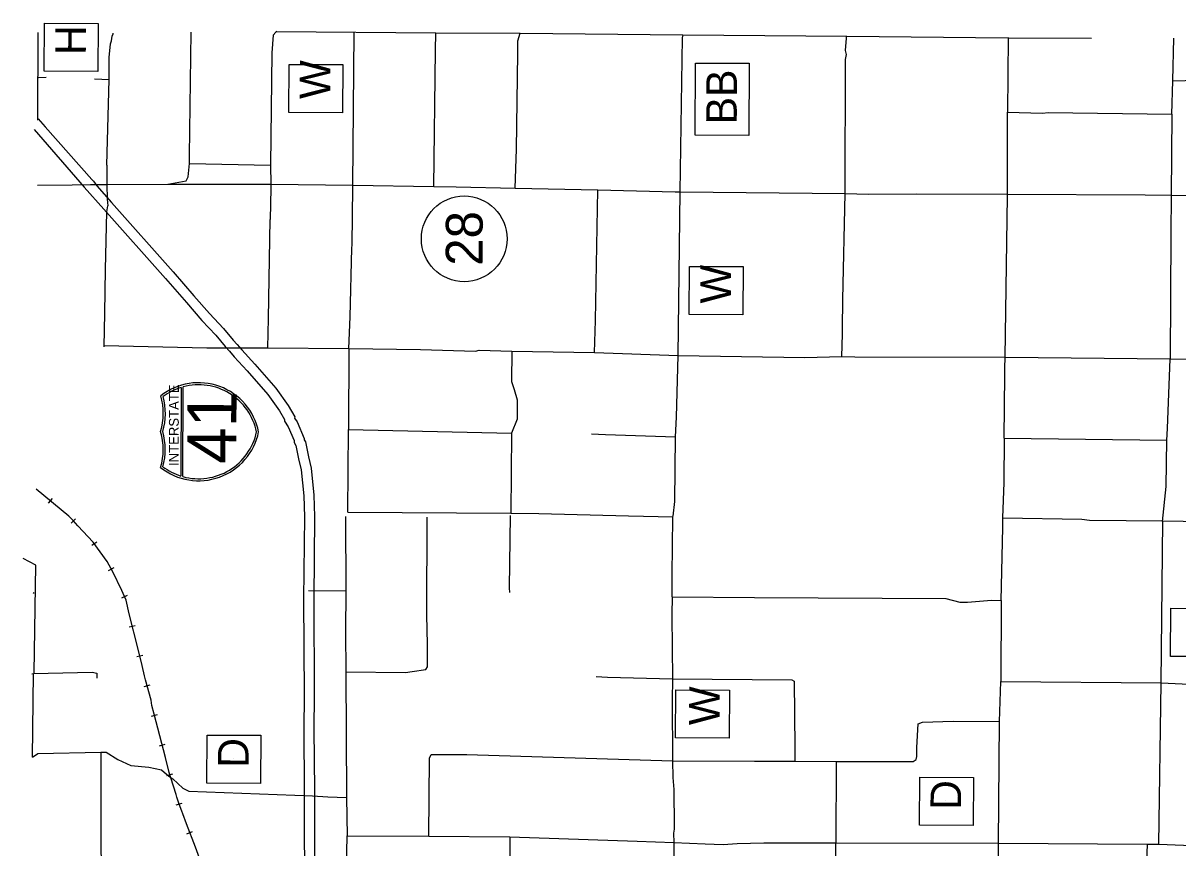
# Model space of a CAD drawing. Extents: x 299354 to 1325680, y 96128 to 228242.
# Drawn here: x 304178 to 341858, y 201335 to 228242 of the extents above; entities that cross this region are included whole.
import ezdxf

# ---------------------------------------------------------------- set-up
doc = ezdxf.new("R2010")
doc.units = 0
for name, color, linetype in [('Level 12', 7, 'Continuous'), ('Level 13', 7, 'Continuous'), ('Level 2', 7, 'Continuous'), ('Level 3', 7, 'Continuous'), ('Level 4', 7, 'Continuous')]:
    doc.layers.add(name, color=color, linetype=linetype)

msp = doc.modelspace()

# ---------------------------------------------------------------- linework, layer by layer
at = {"layer": 'Level 12'}
for p, q in [((318571, 221204), (318571, 221204)), ((309335, 216359), (309327, 213467)), ((309394, 213447), (309402, 216378))]:
    msp.add_line(p, q, dxfattribs=at)
msp.add_circle((318571, 221204), 1398, dxfattribs=at)
for centre, radius, start, end in [((309903, 214511), 1999, 11.3832, 128.1773), ((309903, 214511), 1933, 107.1012, 126.8422), ((309903, 214511), 1933, 11.7868, 105.0434), ((306754, 215504), 1999, 342.8553, 16.8422), ((306754, 215504), 2066, 343.4192, 15.5586), ((309906, 215311), 1999, 231.5152, 348.3093), ((306751, 214335), 1999, 342.8502, 16.8372), ((306751, 214335), 2066, 344.1339, 16.2733), ((309906, 215311), 1933, 254.649, 347.9057), ((309906, 215311), 1933, 232.8503, 252.5912)]:
    msp.add_arc(centre, radius, start, end, dxfattribs=at)
at = {"layer": 'Level 13'}
for p, q in [((305725, 227486), (305725, 227486)), ((313704, 226137), (313704, 226137)), ((326968, 225806), (326968, 225806)), ((326771, 219548), (326771, 219548)), ((326321, 205737), (326321, 205737)), ((311034, 204259), (311034, 204259)), ((334286, 202886), (334286, 202886))]:
    msp.add_line(p, q, dxfattribs=at)
for points in [[(306619, 226665), (304869, 226672), (304875, 228242), (306625, 228234)], [(314598, 225316), (312848, 225323), (312855, 226893), (314605, 226886)], [(327861, 224576), (326111, 224583), (326120, 226938), (327870, 226931)], [(327665, 218726), (325915, 218734), (325922, 220304), (327672, 220296)], [(343369, 207574), (341619, 207581), (341625, 209151), (343375, 209143)], [(327215, 204915), (325465, 204922), (325472, 206492), (327222, 206485)], [(311927, 203437), (310177, 203444), (310184, 205014), (311934, 205007)], [(335179, 202064), (333429, 202071), (333436, 203641), (335186, 203634)]]:
    msp.add_lwpolyline(points, close=True, dxfattribs=at)
at = {"layer": 'Level 2'}
for points in [[(314935, 222887), (314935, 222954), (314980, 227939)], [(325553, 217399), (325618, 222735), (325697, 227762), (325710, 227863)], [(304667, 225119), (304901, 224857), (306419, 223141), (306479, 223084)], [(304538, 224770), (306171, 222894)], [(306479, 223084), (306581, 222931), (307062, 222393), (309069, 220123), (309754, 219341), (310256, 218764), (310712, 218283), (311027, 217903), (311158, 217754), (311313, 217579), (311735, 217116), (312427, 216327), (312823, 215768), (313039, 215396), (313038, 215351), (313117, 215230), (313349, 214690), (313349, 214650), (313388, 214582), (313486, 214096), (313575, 213726), (313664, 212844), (313689, 212144)], [(306171, 222894), (306815, 222174), (308821, 219905), (309506, 219124), (310011, 218542), (310465, 218064), (310776, 217689), (310910, 217536), (311068, 217358), (311489, 216896), (312167, 216122), (312545, 215590), (312708, 215309), (312707, 215254), (312825, 215073), (313018, 214625), (313017, 214564), (313075, 214464), (313164, 214025), (313249, 213671), (313335, 212822), (313359, 212133)], [(306377, 222972), (306911, 222975), (308905, 222983), (311733, 222991), (312266, 222986), (314935, 222954), (317579, 222914), (318313, 222900), (320231, 222858), (322933, 222800), (325451, 222736), (325618, 222735), (330998, 222679), (331757, 222664), (333333, 222667), (336294, 222657), (340790, 222634), (341640, 222626), (346260, 222536), (346552, 222533), (348354, 222517)], [(325463, 214749), (325502, 215382), (325553, 217399)], [(325553, 217399), (329690, 217338), (330891, 217369)], [(330891, 217369), (331317, 217357), (336221, 217347)], [(336221, 217347), (341601, 217291)], [(341493, 214640), (341522, 215015), (341601, 217291)], [(341601, 217291), (346930, 217194)], [(325391, 212159), (325444, 212631), (325463, 214749)], [(341357, 211985), (341480, 213123), (341493, 214640)], [(313359, 212140), (313332, 209460), (313349, 206306), (313338, 205205), (313351, 203218), (313361, 199311)], [(313689, 212137), (313662, 209460), (313679, 206305), (313668, 205204), (313681, 203219), (313691, 199315)], [(325354, 209522), (325361, 210247), (325378, 212114)], [(341316, 206719), (341335, 208836), (341365, 212002)], [(325354, 209522), (325349, 208947), (325348, 208897), (325363, 206847)], [(304466, 207013), (304515, 207019)], [(325363, 206847), (325356, 206155), (325371, 204172)], [(341234, 201453), (341316, 206719)], [(304489, 204294), (304657, 204409), (306709, 204458)], [(306709, 204458), (306884, 204456), (307266, 204219), (307689, 204024), (308281, 203968), (308689, 203881), (308929, 203671), (309062, 203586), (309392, 203283), (309583, 203182), (313618, 203037), (314118, 202999), (314735, 202977)], [(325371, 204172), (325383, 203630), (325413, 203238), (325418, 202038), (325418, 201946), (325400, 201813)], [(314735, 202977), (314757, 201726)], [(314757, 201726), (317418, 201719)], [(317418, 201719), (320061, 201695)], [(320061, 201695), (320037, 199037), (320016, 196795), (320112, 196378)], [(320061, 201695), (324213, 201557)], [(325400, 201813), (325414, 201513)], [(324213, 201557), (325414, 201513)], [(325414, 201513), (325395, 199513), (325418, 198380), (325449, 196296)], [(325414, 201513), (326431, 201471), (327023, 201449), (327482, 201478), (328349, 201503), (330701, 201499)], [(330701, 201499), (336005, 201484)], [(336005, 201484), (340859, 201457)], [(340859, 201457), (341234, 201453)], [(341234, 201453), (343927, 201346)]]:
    msp.add_lwpolyline(points, dxfattribs=at)
at = {"layer": 'Level 3'}
for p, q in [((304660, 225072), (304668, 227932)), ((304489, 204294), (304522, 207019))]:
    msp.add_line(p, q, dxfattribs=at)
at = {"layer": 'Level 4'}
for p, q in [((341691, 226353), (341721, 227745)), ((305004, 212578), (305132, 212732)), ((305746, 211929), (305892, 212065)), ((306419, 211207), (306581, 211323)), ((306968, 210387), (307144, 210484)), ((307396, 209494), (307580, 209574)), ((307642, 208543), (307836, 208593)), ((307888, 207575), (308082, 207623)), ((308128, 206603), (308321, 206654)), ((308368, 205632), (308561, 205683)), ((308623, 204665), (308817, 204716)), ((308871, 203695), (309063, 203749)), ((309172, 202739), (309363, 202798)), ((309524, 201795), (309710, 201868))]:
    msp.add_line(p, q, dxfattribs=at)
for points in [[(312457, 227972), (312420, 227946), (312335, 227847), (312297, 227272), (312247, 223612)], [(306984, 226401), (306990, 227118), (307028, 227560), (307062, 227660), (307080, 227810), (307114, 227893), (307116, 227918)], [(309603, 223660), (309606, 223927), (309666, 227943)], [(312437, 227963), (317642, 227923)], [(317634, 227348), (317641, 227923)], [(317641, 227923), (320393, 227908)], [(320319, 227246), (320324, 227659), (320396, 227916)], [(320393, 227908), (325709, 227858)], [(325709, 227858), (331050, 227818)], [(330891, 217369), (330915, 218094), (330915, 218177), (330916, 218277), (330925, 219228), (330998, 222679), (331012, 227056), (331047, 227222), (331015, 227348), (331043, 227748), (331043, 227821)], [(331050, 227818), (336305, 227766)], [(336324, 227774), (336301, 225333)], [(336305, 227766), (339042, 227749)], [(317579, 222914), (317634, 227348)], [(320231, 222858), (320276, 224133), (320319, 227246)], [(304680, 226472), (304925, 226473)], [(341664, 225269), (341691, 226353), (342909, 226392), (343110, 226540), (346505, 226527)], [(306512, 226423), (306984, 226401)], [(306909, 223609), (306984, 226401)], [(336221, 217347), (336293, 222599), (336294, 222657), (336301, 225333)], [(336301, 225333), (337444, 225307)], [(337444, 225307), (337628, 225322), (341664, 225269)], [(341664, 225269), (341640, 222626), (341631, 221372)], [(306909, 223609), (306911, 222975)], [(308905, 222983), (309498, 223094), (309566, 223227), (309603, 223660)], [(309603, 223660), (312247, 223612)], [(312247, 223612), (312266, 222986), (312257, 222853), (312239, 221836)], [(304646, 222955), (306911, 222975)], [(306911, 222975), (306924, 222500), (306938, 222283)], [(314804, 217628), (314846, 218661), (314900, 220895), (314918, 221012), (314935, 222887)], [(322827, 217499), (322853, 218541), (322933, 222800)], [(306822, 217682), (306848, 218782), (306861, 220208), (306912, 222083), (306938, 222283)], [(312160, 217651), (312185, 218602), (312239, 221836)], [(341631, 221372), (341601, 217291)], [(306823, 217722), (310175, 217652), (311034, 217645)], [(310998, 217645), (312160, 217651)], [(312160, 217651), (314804, 217628)], [(314804, 217628), (314797, 214985)], [(314804, 217628), (317147, 217591), (318940, 217541), (319057, 217574), (320125, 217539)], [(320125, 217539), (320116, 216547), (320205, 216288), (320302, 215954), (320296, 215320), (320117, 214863)], [(320125, 217539), (322827, 217499)], [(322827, 217499), (325553, 217399)], [(336189, 214704), (336208, 216772), (336209, 216980), (336221, 217347)], [(314772, 212284), (314797, 214985)], [(314797, 214985), (320117, 214863)], [(320117, 214863), (320094, 212254)], [(322728, 214840), (323186, 214819), (325463, 214749)], [(336189, 214704), (336176, 213253), (336138, 212098)], [(336189, 214704), (341493, 214640)], [(305673, 212156), (304606, 213036)], [(310264, 200109), (309800, 201363), (309507, 202116), (309385, 202450), (309352, 202534), (309271, 202759), (309198, 202993), (309174, 203077), (308995, 203620), (308947, 203796), (308826, 204288), (308455, 205692), (308383, 205984), (308351, 206151), (308174, 206819), (308142, 206953), (308062, 207287), (307933, 207813), (307635, 208974), (307539, 209417), (307400, 209735), (307106, 210346), (306925, 210673), (306469, 211308), (305963, 211842), (305806, 212011), (305673, 212156), (304606, 213036)], [(307539, 209417), (307400, 209735), (307106, 210346), (306925, 210673), (306469, 211308), (305963, 211842), (305806, 212011), (305673, 212156)], [(314701, 212148), (314706, 209719)], [(314772, 212284), (320094, 212254)], [(320067, 212174), (320038, 209822), (320051, 209670)], [(320094, 212254), (321011, 212245), (323930, 212170), (325389, 212140)], [(314706, 207077), (316650, 207059), (316875, 207091), (317318, 207153), (317368, 207245), (317375, 207969), (317351, 208936), (317363, 212120)], [(336087, 209408), (336142, 211783), (336145, 212100), (338721, 212060), (338971, 212024), (341365, 212002)], [(341365, 212002), (346701, 211921)], [(304540, 207043), (304590, 210555), (304178, 210773)], [(304507, 209667), (304539, 209644)], [(313488, 209730), (314706, 209719)], [(314706, 209719), (314702, 208385)], [(325354, 209522), (328048, 209498), (334286, 209475), (334743, 209354), (334993, 209352), (335778, 209411), (336087, 209408)], [(308351, 206151), (308174, 206819), (308142, 206953), (308062, 207287), (307933, 207813), (307635, 208974), (307539, 209417)], [(336087, 209408), (336079, 206767)], [(314702, 208385), (314706, 207077)], [(304515, 207019), (306433, 207068), (306583, 207034), (306581, 206867)], [(314706, 207077), (314735, 202977)], [(322879, 206931), (323245, 206900), (325363, 206847)], [(325363, 206847), (329257, 206812), (329332, 206778), (329362, 204611), (329358, 204169)], [(336042, 205459), (336079, 206767)], [(336079, 206767), (341316, 206719)], [(341316, 206719), (343583, 206616), (346669, 206588)], [(308826, 204288), (308455, 205692), (308383, 205984), (308351, 206151)], [(330709, 204157), (333219, 204151), (333320, 204217), (333337, 204317), (333340, 204608), (333381, 205383), (333523, 205432), (334524, 205472), (336042, 205459)], [(336005, 201484), (336042, 205459)], [(306709, 204458), (306719, 201866), (306722, 200357), (306746, 199407), (306761, 199240), (306819, 199156), (306969, 199105), (307169, 199103)], [(309198, 202993), (309174, 203077), (308995, 203620), (308947, 203796), (308826, 204288)], [(317418, 201719), (317441, 204260), (317492, 204377)], [(317492, 204377), (318660, 204383), (325371, 204172)], [(325371, 204172), (328048, 204164), (329358, 204169)], [(329358, 204169), (330709, 204157)], [(330709, 204157), (330701, 201499)], [(310411, 199782), (310264, 200109), (309800, 201363), (309507, 202116), (309385, 202450), (309352, 202534), (309271, 202759), (309198, 202993)], [(314699, 199052), (314757, 201726)], [(330650, 197757), (330701, 201499)], [(335931, 195268), (336005, 201484)], [(340859, 201457), (340839, 201165), (340818, 200690), (340783, 200457), (340748, 200358), (340502, 199818), (340281, 199462), (339970, 199123), (339884, 198890), (339862, 198299), (339943, 198057), (340298, 197595), (340430, 197494), (340612, 197309), (340661, 197225), (341149, 196729), (341354, 196402), (341419, 196201), (341405, 194643)]]:
    msp.add_lwpolyline(points, dxfattribs=at)

# ---------------------------------------------------------------- texts
at = {"layer": 'Level 12'}
for s, height, rotation, p in [('28', 1200, 89.767, (319167, 220323)), ('INTERSTATE', 319.9, 89.8462, (309253, 213793)), ('41', 1599.6, 89.8462, (311136, 213860))]:
    msp.add_text(s, height=height, rotation=rotation, dxfattribs=at).set_placement(p)
at = {"layer": 'Level 13'}
for s, p in [('H', (306224, 227201)), ('W', (314203, 225765)), ('BB', (327465, 224939)), ('W', (327270, 219090)), ('W', (326907, 205337)), ('D', (311532, 203949)), ('D', (334784, 202576))]:
    msp.add_text(s, height=1000, rotation=89.767, dxfattribs=at).set_placement(p)

doc.saveas('drawing.dxf')
